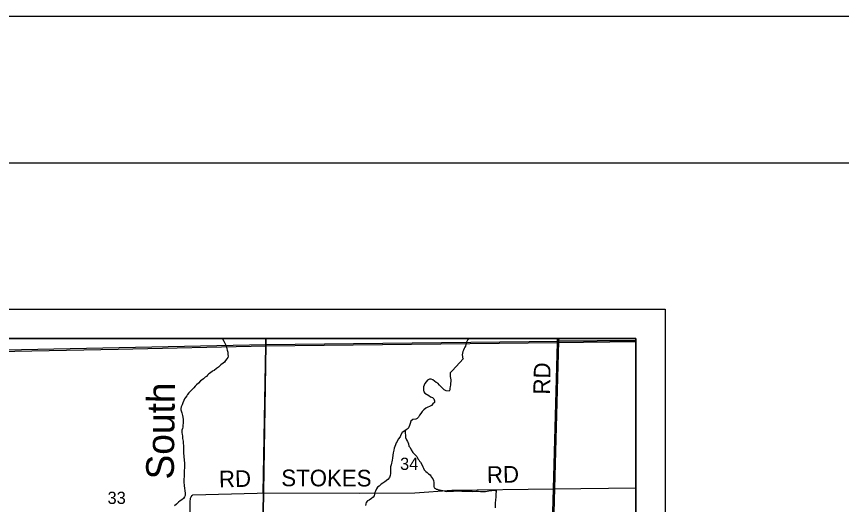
# Model space of a CAD drawing. Extents: x 36.7 to 70.7, y 0 to 22.
# Drawn here: x 43.478 to 46.296, y 20.33 to 21.997 of the extents above; entities that cross this region are included whole.
import ezdxf

# ---------------------------------------------------------------- set-up
doc = ezdxf.new("R2010")
doc.units = 0
for name, color, linetype in [('Default', 7, 'Continuous'), ('GM_X_County_Road', 7, 'Continuous'), ('GM_X_County_Road_Text', 7, 'Continuous'), ('GM_X_Minor_River', 7, 'Continuous'), ('GM_X_Minor_River_Text', 7, 'Continuous'), ('GM_X_Section', 7, 'Continuous'), ('GM_X_Section_Text', 7, 'Continuous'), ('GM_X_Township_Road', 7, 'Continuous'), ('GM_X_Township_Road_Text', 7, 'Continuous'), ('SH_Border', 7, 'Continuous'), ('SH_Cut_Line', 7, 'Continuous'), ('SH_Data', 7, 'Continuous')]:
    doc.layers.add(name, color=color, linetype=linetype)

msp = doc.modelspace()

# ---------------------------------------------------------------- linework, layer by layer
at = {"layer": 'Default'}
for points in [[(44.3297, 20.8969), (43.3265, 20.8969), (43.3259, 20.8559), (44.3293, 20.877)], [(45.3298, 20.8969), (44.3297, 20.8969), (44.3293, 20.877), (45.3296, 20.8874)], [(45.5934, 19.886), (45.5934, 20.8905), (45.3296, 20.8874), (45.3017, 19.8821)], [(45.5934, 20.8905), (45.5934, 20.8969), (45.3298, 20.8969), (45.3296, 20.8874)]]:
    msp.add_lwpolyline(points, close=True, dxfattribs=at)
at = {"layer": 'GM_X_County_Road'}
msp.add_lwpolyline([(44.0658, 19.8612), (44.0684, 20.1426), (44.0712, 20.3408), (44.0721, 20.3499), (44.0725, 20.3518), (44.0729, 20.3545), (44.0741, 20.3564), (44.0776, 20.3613), (44.0799, 20.3631), (44.2998, 20.3691), (44.3207, 20.3695), (44.3292, 20.8716), (44.3295, 20.8969)], dxfattribs=at)
at = {"layer": 'GM_X_Minor_River'}
for points in [[(44.1808, 20.8969), (44.1817, 20.8957), (44.1857, 20.8885), (44.1887, 20.8835), (44.1906, 20.8789), (44.1928, 20.874), (44.1946, 20.8675), (44.1964, 20.8621), (44.1979, 20.8572), (44.2001, 20.8507), (44.2001, 20.8465), (44.1993, 20.842), (44.2003, 20.8371), (44.1995, 20.8325), (44.1957, 20.8276), (44.1922, 20.822), (44.188, 20.8167), (44.1834, 20.8133), (44.1753, 20.8069), (44.1677, 20.7991), (44.1604, 20.795), (44.1531, 20.7878), (44.147, 20.7852), (44.1401, 20.7796), (44.1348, 20.7766), (44.1298, 20.7718), (44.1263, 20.7676), (44.1217, 20.765), (44.1171, 20.759), (44.1125, 20.7564), (44.1068, 20.7519), (44.0991, 20.7444), (44.0926, 20.7384), (44.0884, 20.7342), (44.083, 20.7286), (44.0792, 20.7245), (44.0719, 20.7177), (44.0665, 20.7117), (44.0615, 20.7057), (44.0592, 20.7015), (44.0549, 20.6951), (44.0519, 20.6906), (44.0491, 20.6857), (44.0456, 20.677), (44.0433, 20.6702), (44.0402, 20.6634), (44.0393, 20.6581), (44.0393, 20.6535), (44.0426, 20.6432), (44.0437, 20.6383), (44.0444, 20.6337), (44.0455, 20.6284), (44.0469, 20.6204), (44.0472, 20.6124), (44.0467, 20.6071), (44.0463, 20.6026), (44.0459, 20.5984), (44.0454, 20.5939), (44.0443, 20.5893), (44.0431, 20.584), (44.0426, 20.5764), (44.0436, 20.5692), (44.0443, 20.5643), (44.045, 20.5559), (44.0468, 20.5468), (44.0471, 20.5399), (44.0478, 20.5308), (44.0481, 20.5247), (44.0479, 20.5137), (44.0483, 20.5084), (44.0486, 20.5035), (44.0489, 20.497), (44.0496, 20.4906), (44.0503, 20.4845), (44.051, 20.4795), (44.0513, 20.4735), (44.0516, 20.4685), (44.0515, 20.4583), (44.0511, 20.4537), (44.0506, 20.4473), (44.0505, 20.4382), (44.0501, 20.4332), (44.0498, 20.4089), (44.0504, 20.393), (44.0511, 20.3873), (44.0532, 20.3751), (44.0535, 20.3702)], [(45.0219, 20.8969), (45.0197, 20.8938), (45.0163, 20.8873), (45.0141, 20.882)], [(45.0141, 20.882), (45.0115, 20.8714), (45.0096, 20.8672), (45.007, 20.863), (45.0047, 20.8573), (45.0028, 20.8523), (45.0013, 20.8466), (45.0006, 20.8413), (45.001, 20.836), (45.0014, 20.8318), (45.0037, 20.8276), (44.9671, 20.7877)], [(44.968, 20.7886), (44.9591, 20.7799), (44.9587, 20.7746), (44.9597, 20.7678), (44.9604, 20.7621), (44.9611, 20.756), (44.961, 20.7499), (44.9606, 20.745), (44.9602, 20.7393), (44.9593, 20.7321), (44.9585, 20.7272), (44.9577, 20.7219), (44.9554, 20.717), (44.9455, 20.7182), (44.9391, 20.7221), (44.9327, 20.7278), (44.9226, 20.7371), (44.917, 20.7447), (44.9113, 20.7467), (44.9061, 20.7517), (44.9004, 20.7559), (44.8944, 20.7586), (44.8891, 20.7587), (44.8814, 20.755), (44.8768, 20.7489), (44.8726, 20.7429), (44.8702, 20.7376), (44.8683, 20.7319), (44.8675, 20.7259), (44.8678, 20.7206), (44.8696, 20.7152), (44.873, 20.7103), (44.8862, 20.7021), (44.8922, 20.6983), (44.8986, 20.6952), (44.9039, 20.6906), (44.9057, 20.6845), (44.9052, 20.6788), (44.9002, 20.6735), (44.8949, 20.6686), (44.8766, 20.6594), (44.8689, 20.6537), (44.8639, 20.6477), (44.8589, 20.6409), (44.8547, 20.6353), (44.8508, 20.6289), (44.8469, 20.6236), (44.842, 20.6214), (44.8321, 20.6207), (44.8252, 20.6144), (44.8221, 20.6068), (44.8205, 20.5996), (44.8185, 20.5947), (44.8154, 20.5894), (44.8093, 20.5849), (44.804, 20.5816), (44.7948, 20.576), (44.7902, 20.568), (44.7878, 20.5616), (44.7817, 20.5537), (44.7778, 20.5454), (44.7751, 20.5405), (44.772, 20.5344), (44.7696, 20.528), (44.7684, 20.5227), (44.7664, 20.5155), (44.7648, 20.5064), (44.7636, 20.4985)], [(44.805, 20.5822), (44.8069, 20.5585), (44.8096, 20.5505), (44.8138, 20.5456), (44.8142, 20.543), (44.8165, 20.5369), (44.8185, 20.5289), (44.8223, 20.5248), (44.8265, 20.5164), (44.8319, 20.5073), (44.8364, 20.5036), (44.8448, 20.4937), (44.8479, 20.4896), (44.849, 20.4865), (44.8525, 20.4827), (44.8548, 20.4778), (44.8578, 20.4744), (44.8624, 20.4668), (44.8655, 20.4585), (44.8686, 20.454), (44.8709, 20.4486), (44.8732, 20.4445), (44.8762, 20.4426), (44.8808, 20.4396), (44.8854, 20.435), (44.8903, 20.4313), (44.8934, 20.4275), (44.8945, 20.4248), (44.9003, 20.4176), (44.9018, 20.4116), (44.903, 20.4047), (44.903, 20.3979), (44.9038, 20.3918), (44.9046, 20.3873), (44.9088, 20.3843), (44.9118, 20.3827), (44.9145, 20.382), (44.919, 20.3805), (44.9228, 20.3798), (44.927, 20.379), (44.9308, 20.3783), (44.9346, 20.3779), (44.9388, 20.3768), (44.946, 20.3749), (44.9525, 20.3757), (44.9677, 20.3754), (44.9703, 20.3758), (44.9817, 20.3766), (44.9863, 20.3763), (44.9992, 20.3756), (45.0022, 20.376), (45.0166, 20.3753), (45.0329, 20.3753), (45.036, 20.375), (45.0493, 20.3754), (45.0565, 20.3751), (45.0626, 20.3747), (45.0667, 20.3744), (45.0793, 20.3748), (45.0914, 20.3768), (45.1016, 20.3783), (45.1077, 20.3791), (45.1126, 20.3784), (45.1161, 20.3776), (45.1154, 20.3636), (45.1154, 20.359), (45.1147, 20.3545), (45.1139, 20.3472), (45.114, 20.3438), (45.1132, 20.3374), (45.1133, 20.3184)], [(44.7636, 20.4985), (44.7619, 20.4879), (44.7607, 20.4814), (44.7599, 20.4757), (44.7591, 20.4708), (44.7575, 20.4655), (44.7559, 20.4587), (44.7555, 20.4534), (44.755, 20.4477), (44.7553, 20.4412), (44.7553, 20.4359), (44.7541, 20.4295), (44.7517, 20.4227), (44.7467, 20.4159), (44.736, 20.408), (44.7295, 20.4032), (44.7234, 20.3998), (44.7165, 20.3923), (44.7111, 20.3893), (44.7073, 20.3833), (44.7038, 20.3761), (44.7014, 20.3712), (44.699, 20.3602), (44.6963, 20.3546), (44.691, 20.3501), (44.6822, 20.3452), (44.6768, 20.3426), (44.6722, 20.337), (44.6714, 20.332), (44.6694, 20.3264)], [(44.0535, 20.3702), (44.0535, 20.366), (44.0534, 20.3611), (44.0518, 20.3562), (44.0484, 20.3501), (44.0426, 20.3464), (44.0365, 20.3423), (44.0311, 20.3382), (44.0246, 20.3314), (44.0174, 20.3258)]]:
    msp.add_lwpolyline(points, dxfattribs=at)
at = {"layer": 'GM_X_Section'}
for points in [[(45.3296, 20.8874), (45.3017, 19.8821), (45.2759, 19.881), (44.3136, 19.8697), (44.3293, 20.877)], [(44.3293, 20.877), (44.3136, 19.8697), (44.2753, 19.8692), (43.3171, 19.855), (43.3259, 20.8559)]]:
    msp.add_lwpolyline(points, close=True, dxfattribs=at)
at = {"layer": 'GM_X_Township_Road'}
for p, q in [((44.3292, 20.8716), (45.3255, 20.8829)), ((45.3122, 20.3833), (45.3255, 20.8829)), ((45.3255, 20.8829), (45.3258, 20.8969)), ((45.3255, 20.8829), (45.5934, 20.8867)), ((43.3216, 20.8505), (43.8254, 20.861)), ((43.8254, 20.861), (44.3292, 20.8716)), ((45.2983, 19.8779), (45.3122, 20.3833)), ((45.3122, 20.3833), (45.5934, 20.3868))]:
    msp.add_line(p, q, dxfattribs=at)
for points in [[(43.3189, 19.8494), (44.0245, 19.8612), (44.0656, 19.8618), (45.2722, 19.8781), (45.2981, 19.8785), (45.5934, 19.8832), (45.5934, 20.8969), (41.3748, 20.8969)], [(44.3207, 20.3695), (44.6495, 20.3684), (44.8382, 20.3703), (44.9651, 20.3789), (45.3122, 20.3833)]]:
    msp.add_lwpolyline(points, dxfattribs=at)
at = {"layer": 'SH_Border'}
msp.add_lwpolyline([(38.1934, 21.4969), (70.1934, 21.4969), (70.1934, 0.4969), (38.1934, 0.4969)], close=True, dxfattribs=at)
at = {"layer": 'SH_Cut_Line'}
msp.add_lwpolyline([(36.6934, -0.0031), (70.6934, -0.0031), (70.6934, 21.9969), (36.6934, 21.9969)], close=True, dxfattribs=at)
at = {"layer": 'SH_Data'}
for p, q in [((38.6934, 20.9969), (45.6934, 20.9969)), ((45.6934, 20.9969), (45.6934, 13.9969)), ((38.7934, 20.8969), (45.5934, 20.8969)), ((45.5934, 20.8969), (45.5934, 14.0969))]:
    msp.add_line(p, q, dxfattribs=at)

# ---------------------------------------------------------------- texts
at = {"layer": 'GM_X_County_Road_Text'}
msp.add_text('RD', height=0.05682, rotation=1.4816, dxfattribs=at).set_placement((44.1699, 20.3881))
at = {"layer": 'GM_X_Minor_River_Text'}
msp.add_text('South', height=0.09476, rotation=89.2649, dxfattribs=at).set_placement((44.0149, 20.415))
at = {"layer": 'GM_X_Section_Text'}
for s, p in [('34', (44.788, 20.4481)), ('33', (43.7888, 20.3319))]:
    msp.add_text(s, height=0.04186, rotation=0, dxfattribs=at).set_placement(p)
at = {"layer": 'GM_X_Township_Road_Text'}
for s, rotation, p in [('RD', 88.5193, (45.2997, 20.7049)), ('RD', 0.9881, (45.0851, 20.4033)), ('STOKES', 359.8182, (44.3822, 20.3925))]:
    msp.add_text(s, height=0.05682, rotation=rotation, dxfattribs=at).set_placement(p)

doc.saveas('drawing.dxf')
